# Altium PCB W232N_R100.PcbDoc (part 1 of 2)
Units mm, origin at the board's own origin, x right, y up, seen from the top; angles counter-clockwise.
Board outline 70 x 46.25 mm, 4 copper layers (Top Layer, Layer 1, Layer 2, Bottom Layer), stack 1.584 mm thick; 133 components, 105 nets, 435 pads, 346 vias.
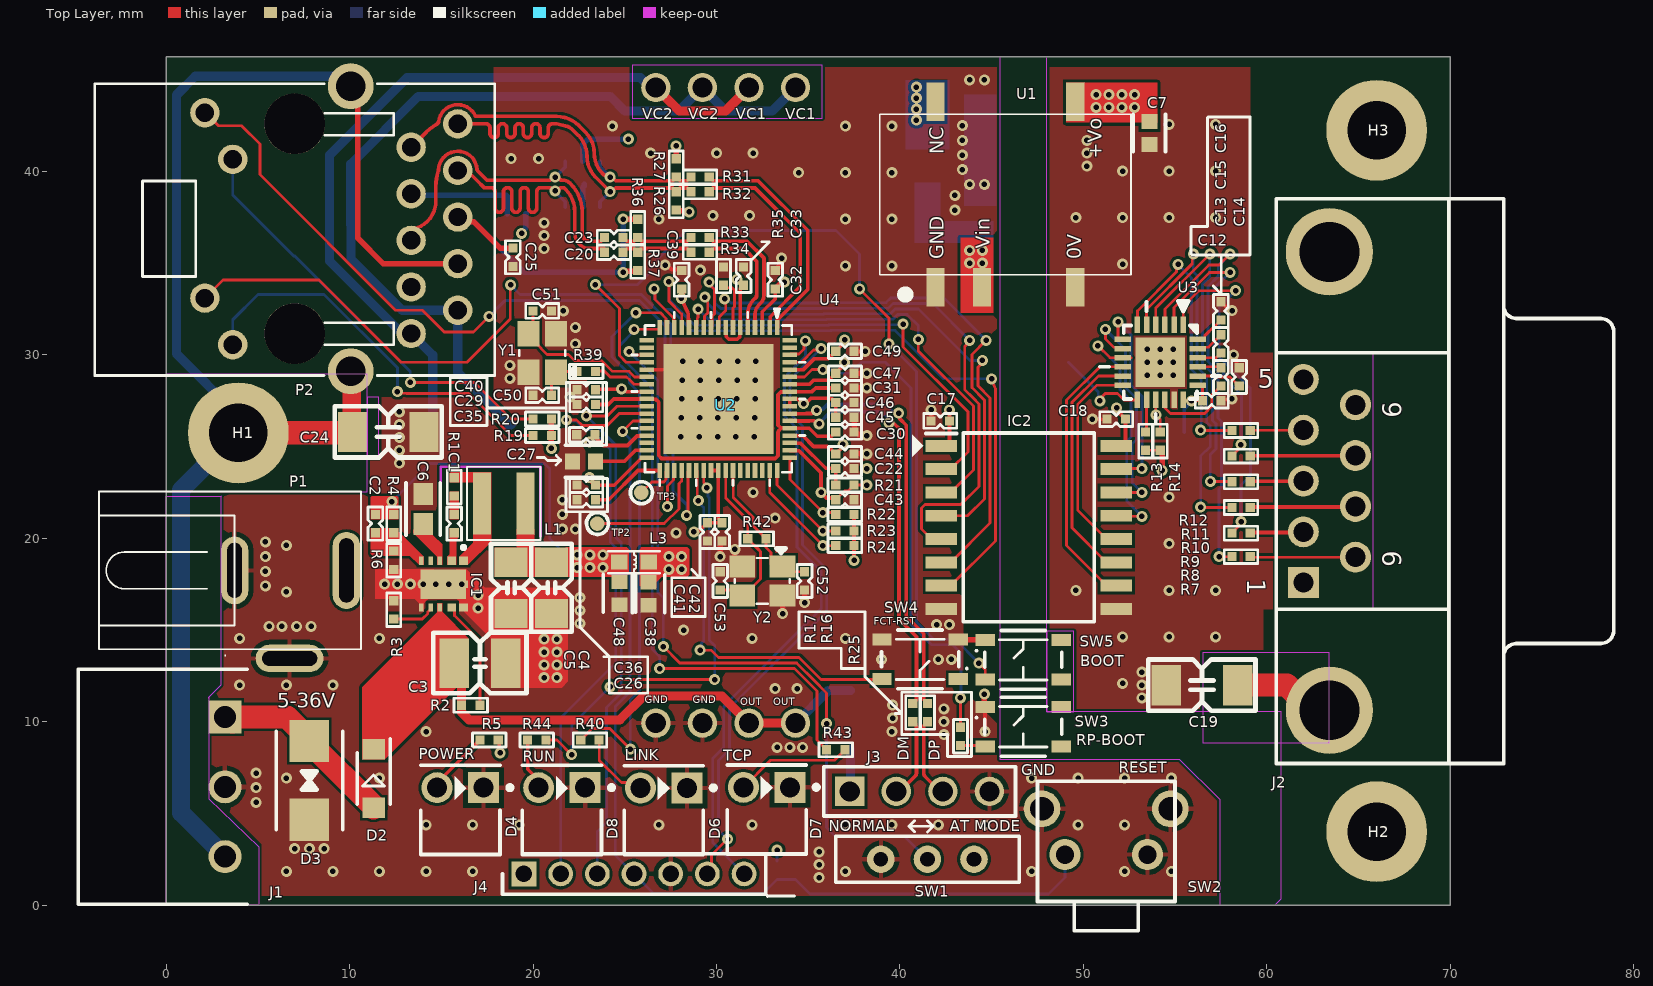
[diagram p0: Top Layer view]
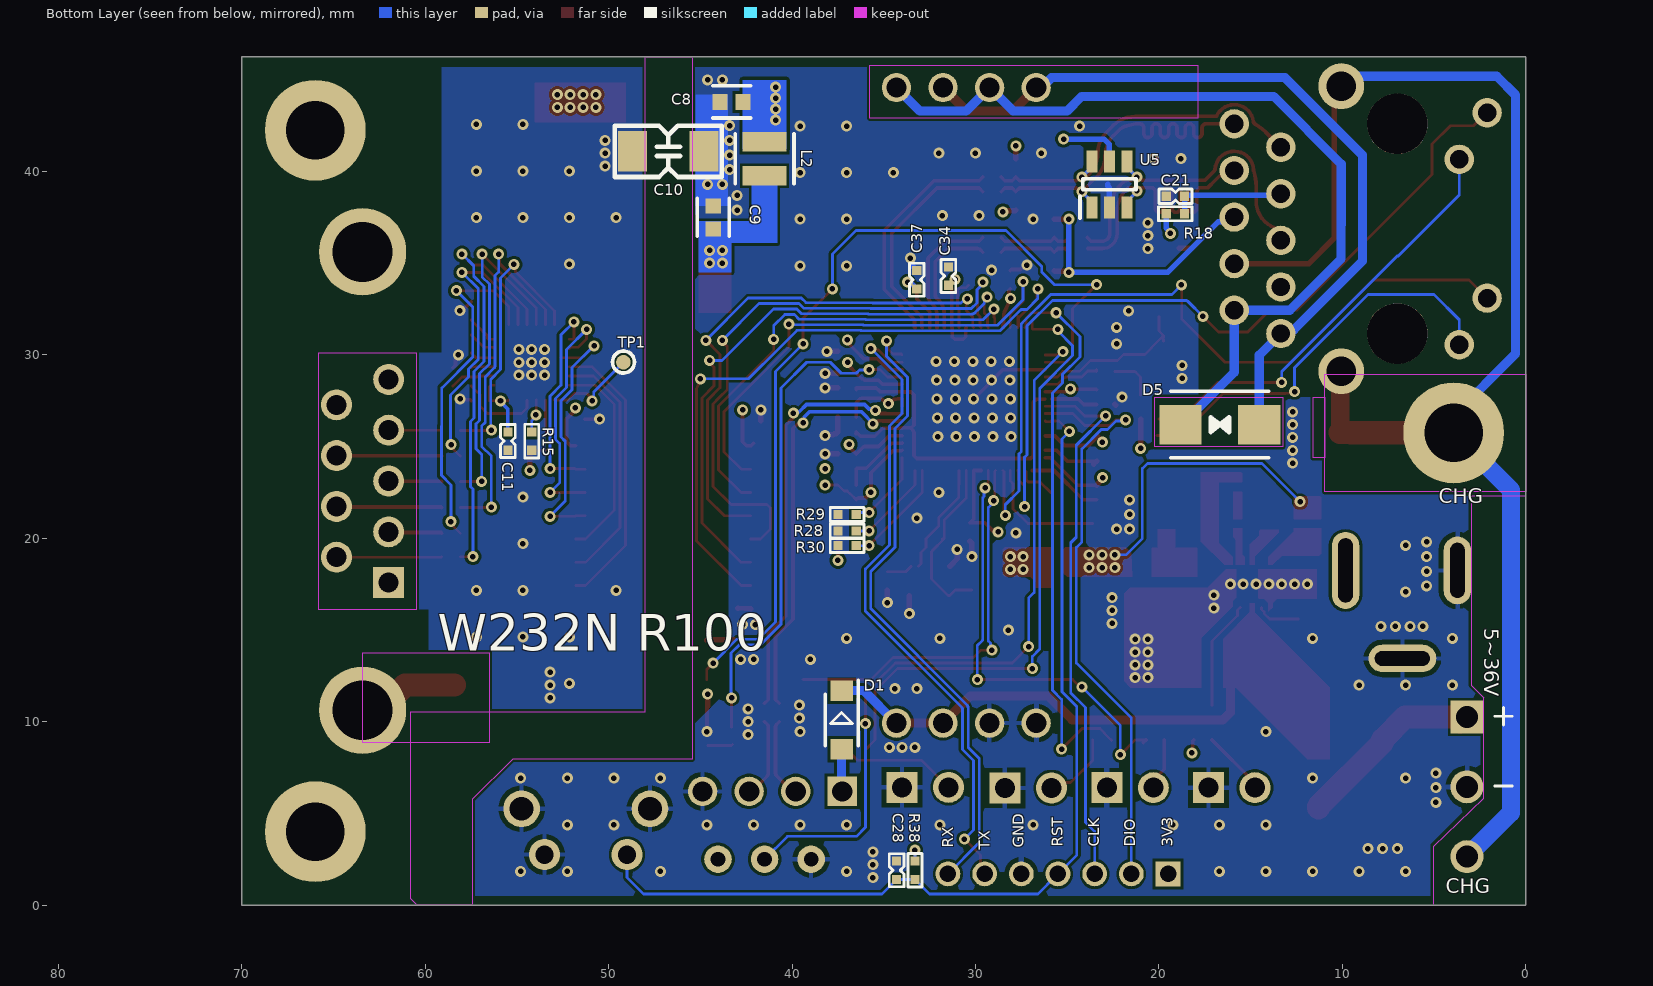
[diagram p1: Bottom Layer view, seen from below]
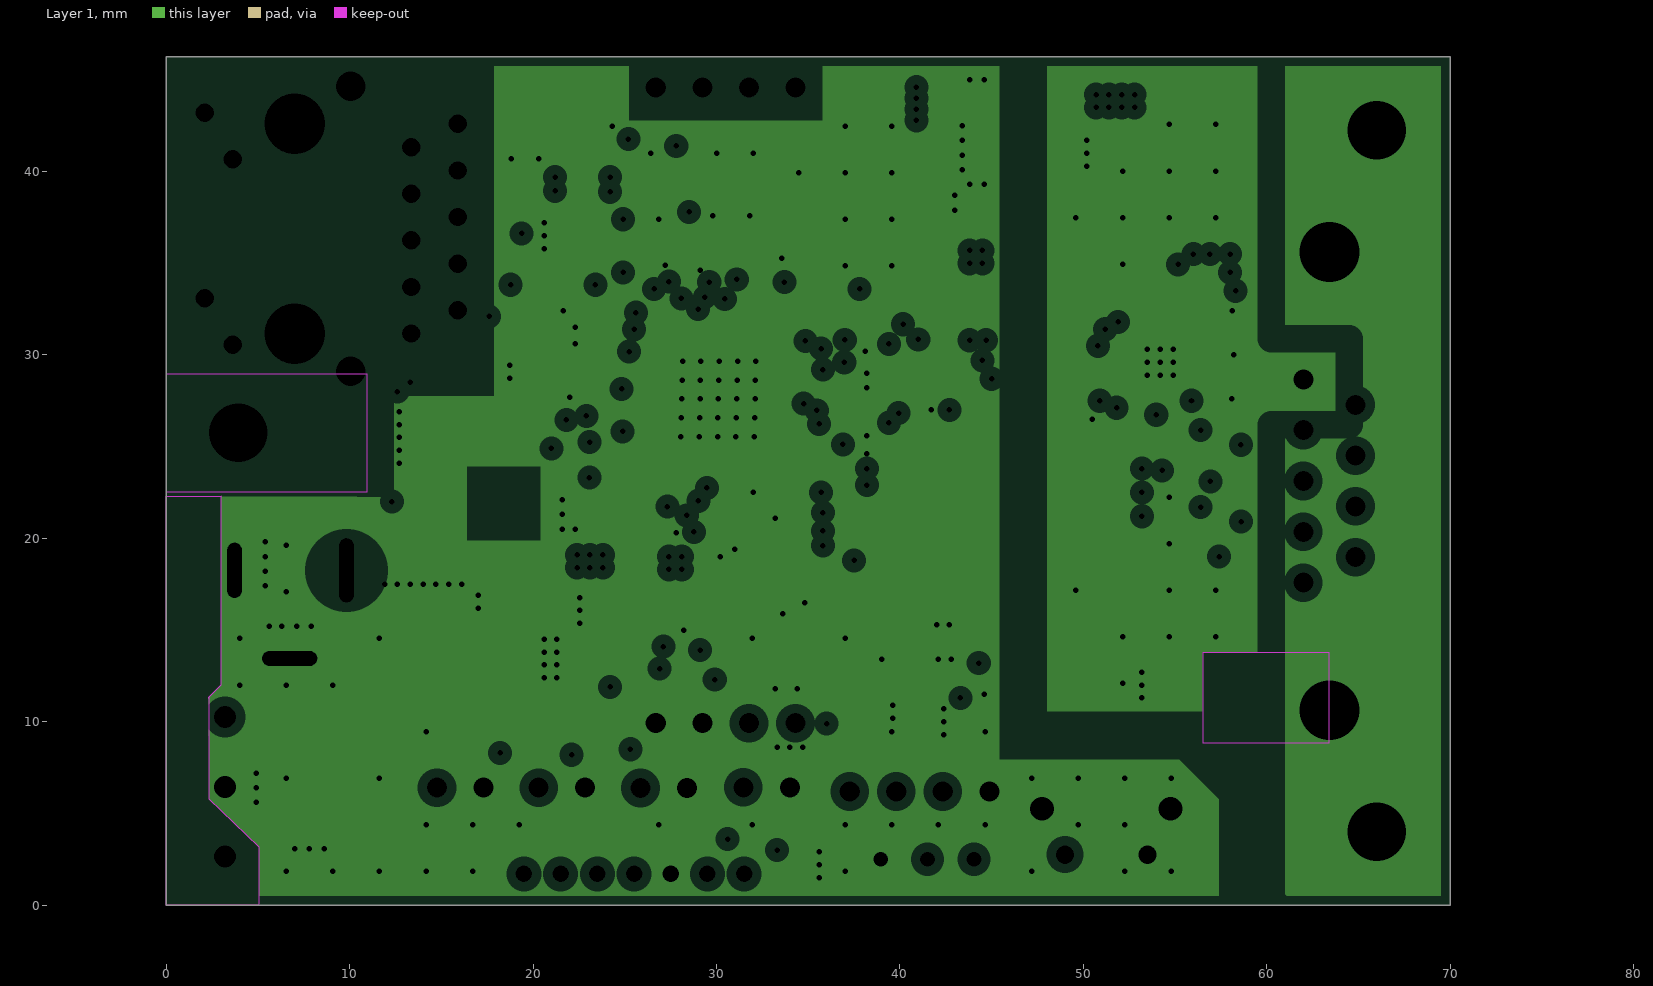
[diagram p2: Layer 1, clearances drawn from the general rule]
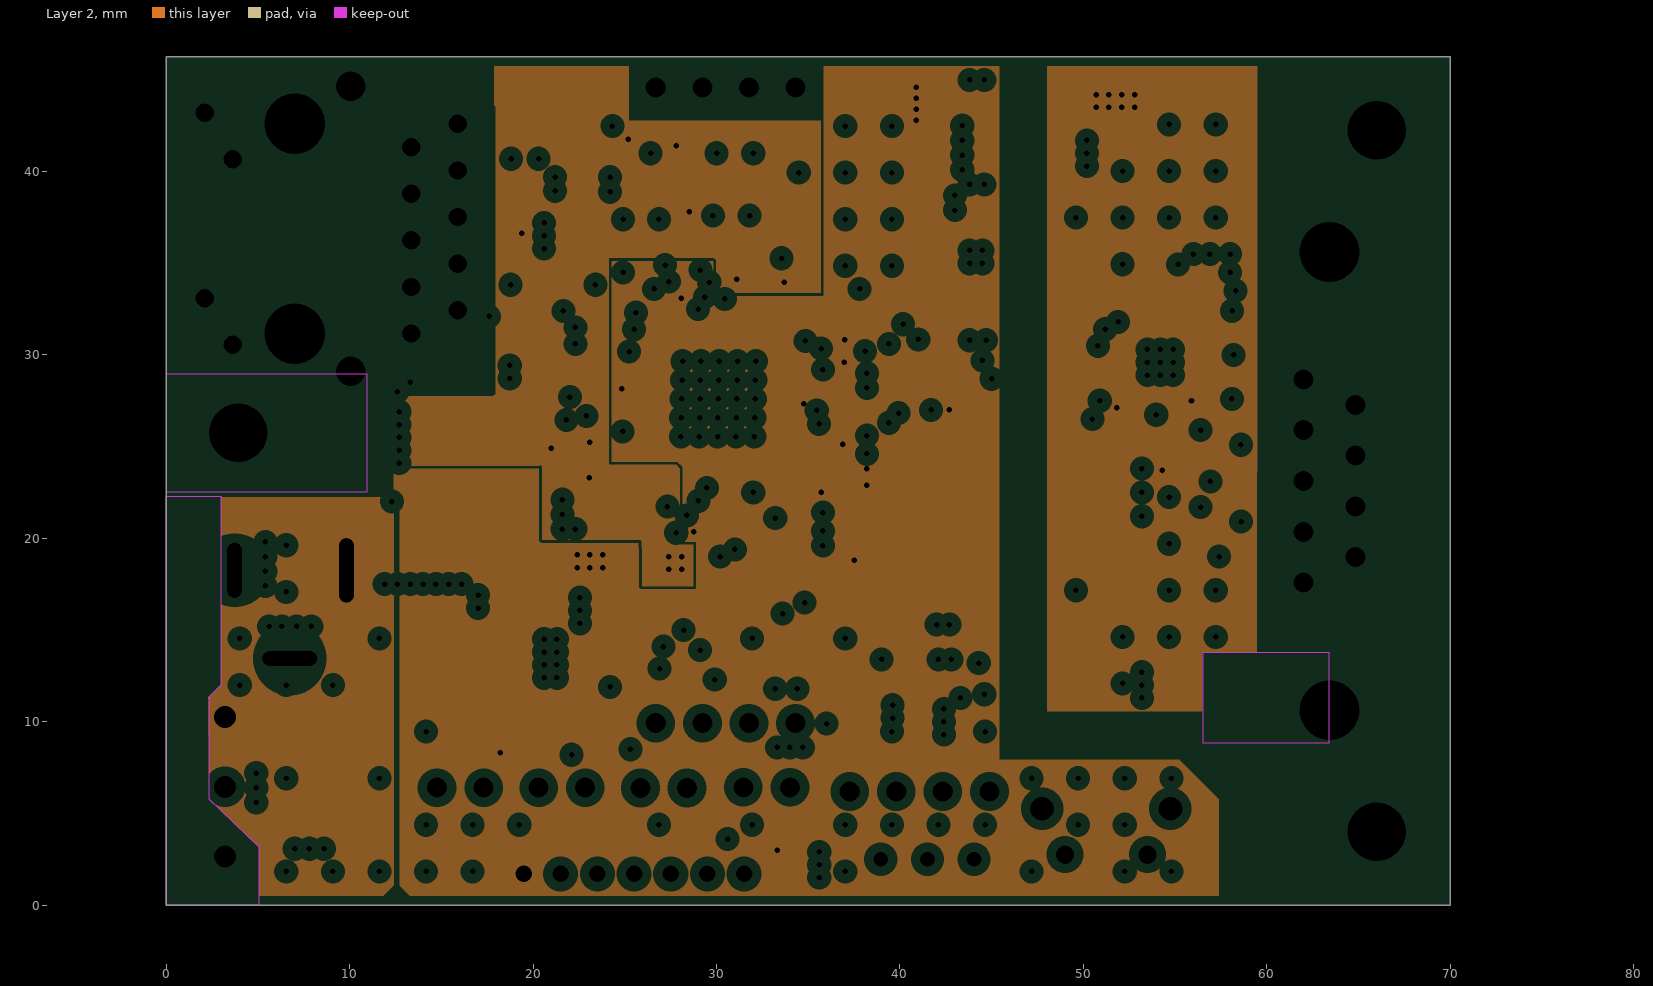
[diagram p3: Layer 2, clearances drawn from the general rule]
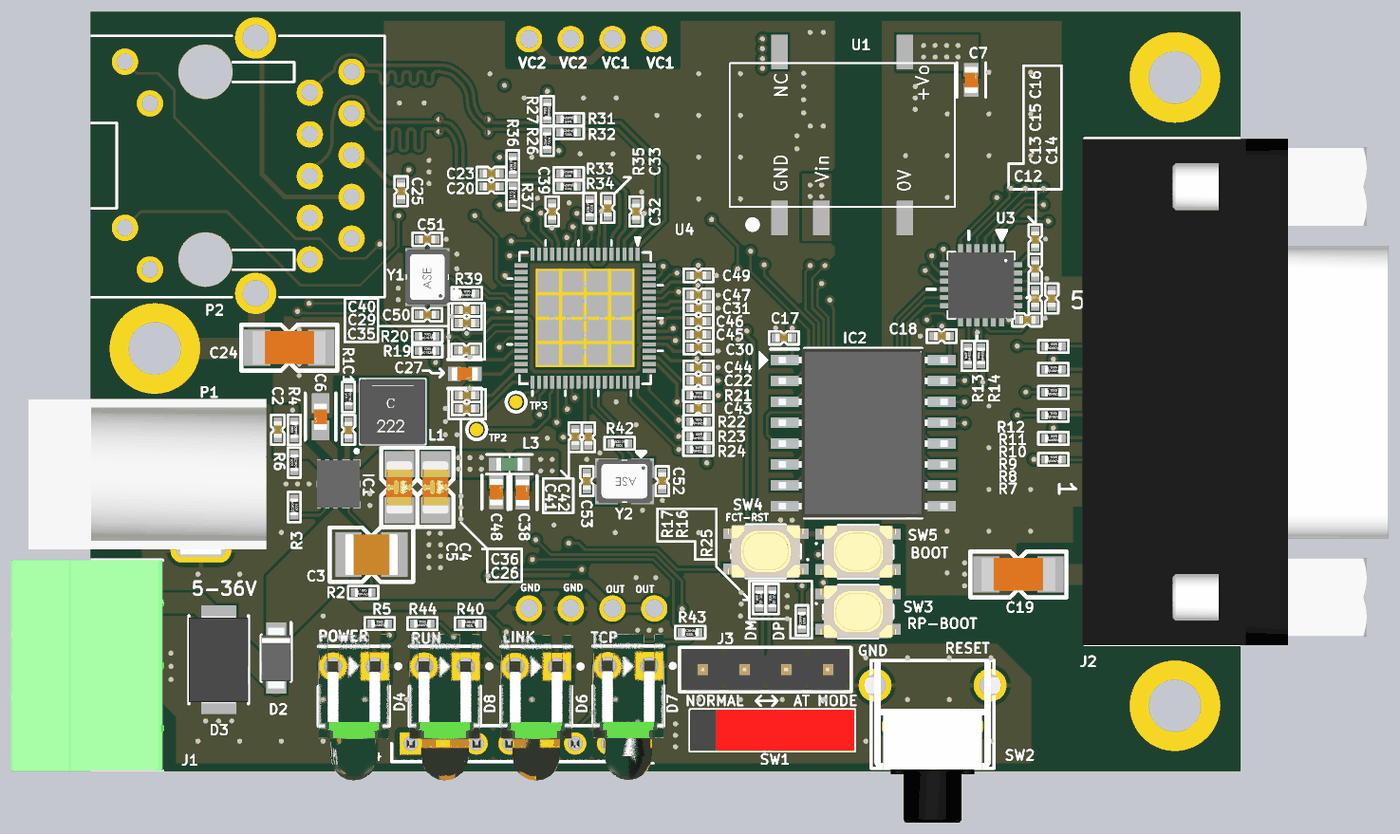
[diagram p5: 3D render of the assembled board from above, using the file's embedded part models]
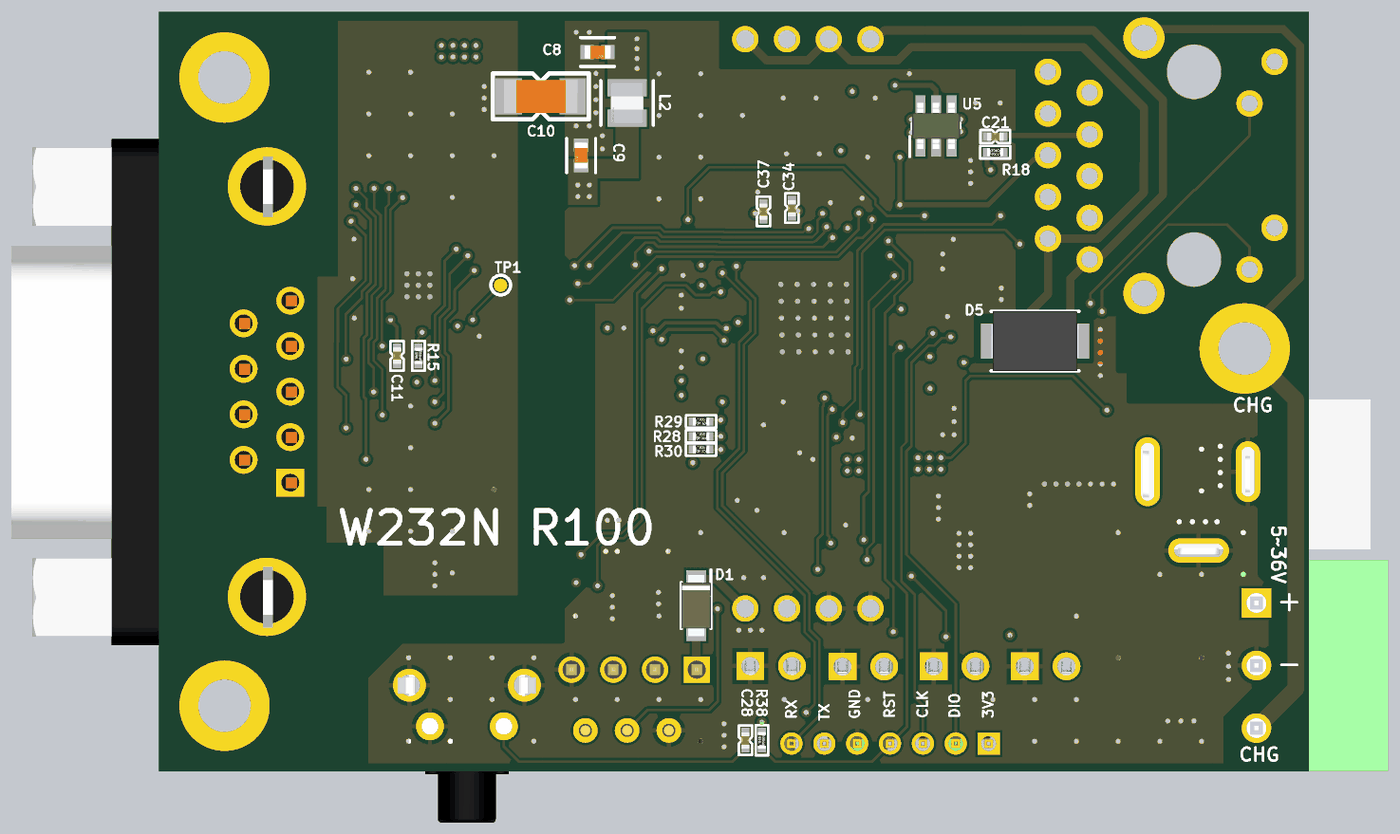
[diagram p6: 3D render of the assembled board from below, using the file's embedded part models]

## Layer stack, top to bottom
Top Solder: solder mask 0.0102, Solder Resist, Dk 3.5
Top Layer: signal copper 0.04
Dielectric 2: prepreg 0.2, PP-022, Dk 4.18
Layer 1: plane copper 0.032, net (Multiple Nets)
Dielectric 1: dielectric 1.04, FR-4, Dk 4.3
Layer 2: plane copper 0.032, net (Multiple Nets)
Dielectric 3: prepreg 0.2, PP-022, Dk 4.18
Bottom Layer: signal copper 0.04
Bottom Solder: solder mask 0.0102, Solder Resist, Dk 3.5

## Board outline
0,0 0,46.25 70,46.25 70,0

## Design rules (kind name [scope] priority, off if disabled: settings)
BoardOutlineClearance [InNetClass('All Nets')] p1: gap=0.3 ignorepadtopadclearanceinfootprint=FALSE
Clearance [All] p1: gap=0.15 ignorepadtopadclearanceinfootprint=FALSE except(0: Arc-Text Arc-Hole Track-Text Track-Hole SMDPad-Hole THPad-Hole Via-Hole Fill-Hole Poly-Hole Region-Hole Text-Hole; 0.1: SMDPad-Text THPad-Text Via-Text Fill-Text Poly-Text Region-Text Text-Text)
DiffPairsRouting [All] p1: maxlimit=0.2 minlimit=0.2 mostfreqgap=0.2 toplayer_minwidth=0.2 toplayer_maxwidth=0.2 toplayer_prefwidth=0.2 bottomlayer_minwidth=0.2 bottomlayer_maxwidth=0.2 bottomlayer_prefwidth=0.2 maxuncoupledlength=12.7
HoleSize [All] p1: absolutevalues=TRUE maxlimit=5 minlimit=0.025 maxpercent=80.000 minpercent=20.000
MinimumSolderMaskSliver [All] p1: minsoldermaskwidth=0.08
PlaneClearance [All] p1: clearance=0.508
PlaneConnect [All] p1: pad.planeconnectstyle=Relief pad.reliefexpansion=0.508 pad.reliefentries=4 pad.reliefconductorwidth=0.254 pad.reliefairgap=0.254 via.planeconnectstyle=Direct via.reliefexpansion=0.508 via.reliefentries=4 via.reliefconductorwidth=0.254 via.reliefairgap=0.254
PolygonConnect [All] p1: thpad.connectstyle=Relief thpad.reliefconductorwidth=0.254 thpad.reliefentries=4 thpad.polygonreliefangle="90 Angle" thpad.airgapwidth=0.254 smdpad.connectstyle=Direct smdpad.reliefconductorwidth=0.254 smdpad.reliefentries=4 smdpad.polygonreliefangle="90 Angle" smdpad.airgapwidth=0.254 via.connectstyle=Direct via.reliefconductorwidth=0.254 via.reliefentries=4 via.polygonreliefangle="90 Angle" via.airgapwidth=0.254
RoutingVias [All] p1: holewidth=0.3 width=0.6 viastyle="Through Hole" minholewidth=0.3 minwidth=0.6 maxholewidth=0.5 maxwidth=0.8
SilkToSilkClearance [All] p1: silktosilkclearance=0.01
SilkToSolderMaskClearance [IsText] p1: minsilkscreentomaskgap=0.1 clearancetoexposedcopper=TRUE
SolderMaskExpansion [All] p1: expansion=0 istentingtop=FALSE
Width [All] p1: maxlimit=3 minlimit=0.15 preferedwidth=0.152 minimp=50.000000 maximp=50.000000 favimp=50.000000
23 further rules are at their usual default settings.

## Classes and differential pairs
differential pair D: +D_P -D_N
differential pair MDI_R1: +MDI_R1_P -MDI_R1_N
differential pair T: +T_P -T_N
differential pair R: +R_P -R_N
differential pair MDI_T: +MDI_T_P -MDI_T_N
differential pair MDI_R: +MDI_R_P -MDI_R_N

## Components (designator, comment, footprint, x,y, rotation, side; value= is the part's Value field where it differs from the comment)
C1 "100nF" CAP-0402 15.7,20.8 r270 top
C2 "15pF" CAP-0402 11.4,20.8 r90 top
C3 "4.7uF / 100V" CAP-1210 17.1,13.2 r180 top
C4 "22uF/10V" CAP-1206 21,17.3 r270 top
C5 "22uF/10V" CAP-1206 18.8,17.3 r270 top
C6 "1uF" CAP-0603-1 14,21.6 r270 top
C7 "10uF/10V" CAP-0603-3 53.6,42.1 r90 top
C8 "4.7uF" CAP-0603-3 43.3,43.8 r180 bottom
C9 "4.7uF" CAP-0603-3 44.3,37.5 r270 bottom
C10 "1nF/2kV" CAP-1808 46.75,41.1 r180 bottom
C11 "100nF" CAP-0402 55.5,25.3 r90 bottom
C12 "100nF" CAP-0402 57,27.5 r0 top
C13 "100nF" CAP-0402 57.5,28.8 r270 top
C14 "100nF" CAP-0402 58.5,28.8 r270 top
C15 "100nF" CAP-0402 57.5,30.6 r90 top
C16 "100nF" CAP-0402 57.5,32.4 r270 top
C17 "100nF" CAP-0402 42.2,26.4 r180 top
C18 "100nF" CAP-0402 51.8,26.5 r0 top
C19 "1nF/2kV" CAP-1808 56.47,11.997 r180 top
C20 "6.8nF" CAP-0402 24.4,35.6 r180 top
C21 "22nF" CAP-0402 19.1,38.65 r180 bottom
C22 "2.2uF" CAP-0402 37,23.8 r180 top
C23 "6.8nF" CAP-0402 24.4,36.4 r180 top
C24 "1nF/2kV" CAP-1808 12.1,25.8 r180 top
C25 "10nF" CAP-0402 18.9,35.325 r90 top
C26 "10nF" CAP-0402 22.9,22.1 r0 top
C27 "4.7uF" CAP-0603-3 22.774,24.2 r0 top
C28 "100nF" CAP-0402 34.3,1.9 r270 bottom
C29 "2.2uF" CAP-0402 22.9,27.3 r0 top
C30 "100nF" CAP-0402 37,25.8 r180 top
C31 "100nF" CAP-0402 37,28.2 r180 top
C32 "100nF" CAP-0402 33.2,34.1 r270 top
C33 "100nF" CAP-0402 31.475,34.3 r270 top
C34 "100nF" CAP-0402 31.475,34.3 r270 bottom
C35 "100nF" CAP-0402 22.875,25.65 r0 top
C36 "100nF" CAP-0402 22.9,22.9 r0 top
C37 "100nF" CAP-0402 33.2,34.1 r270 bottom
C38 "10uF" CAP-0603-3 26.3,16.974 r90 top
C39 "2.2uF" CAP-0402 28.1,34.1 r270 top
C40 "2.2uF" CAP-0402 22.9,28.1 r0 top
C41 "2.2uF" CAP-0402 29.5,20.35 r90 top
C42 "100nF" CAP-0402 30.3,20.35 r90 top
C43 "100nF" CAP-0402 37,22.1 r180 top
C44 "100nF" CAP-0402 37,24.6 r180 top
C45 "100nF" CAP-0402 37,26.6 r180 top
C46 "100nF" CAP-0402 37,27.4 r180 top
C47 "100nF" CAP-0402 37,29 r180 top
C48 "10uF" CAP-0603-3 24.7,17 r90 top
C49 "100nF" CAP-0402 37,30.2 r180 top
C50 "15pF" CAP-0402 20.5,27.8 r0 top
C51 "15pF" CAP-0402 20.5,32.4 r180 top
C52 "18pF" CAP-0402 34.8,17.676 r90 top
C53 "18pF" CAP-0402 30.2,17.676 r270 top
D1 "SS1FN6-M3_I" SODFL3718X108N 37.3,10.1 r270 bottom
D2 "SS1FN6-M3_I" SODFL3718X108N 11.3,6.9 r270 top
D3 "SMBJ36CA" DO-214AA/SMB(TVS) 7.8,6.8 r90 top
D4 "RED" KLH-117 16.03,3.905 r0 top locked
D5 "SMBJ58CA" DO-214AA/SMB(TVS) 16.675,26.2 r0 bottom
D6 "GREEN" KLH-117 27.123,3.891 r0 top locked
D7 "GREEN" KLH-117 32.737,3.927 r0 top locked
D8 "GREEN" KLH-117 21.57,3.905 r0 top locked
H1 "PCB Hole" M3_HOLE 3.92,25.75 r0 top locked
H2 "PCB Hole" M3_HOLE 66,4 r0 top locked
H3 "PCB Hole" M3_HOLE 66,42.25 r0 top locked
IC1 "XC9702A75CDR-G" XC9135B18CDRG 15.1,17.5 r270 top
IC2 "ISO6763DWR" SOIC127P1030X265-16N 47.025,20.595 r0 top
J1 "Terminal_Blocks" 1803280 3.2,10.26 r270 top locked
J2 "D-SUB9-MALE" D-SUB9-MALE 72.92,23.125 r270 top locked
J3 "Pin Header Dip 4x1_2.54mm" Pin-Header(DIP)_4x1_2.54mm 41.07,6.2 r0 top locked
J4 "Pin Header 7x1_2.0mm" Pin-Header(DIP)_7x1_2.0mm 19.5,1.7 r0 top
L1 "VLS4020CX-220M-H" XAL40XX 18.4,21.9 r0 top
L2 "6.8uH" FP-SRN2512-MFG 41.5,40.7 r270 bottom
L3 "HH-1M1608-121JT" IND-0603 25.5,18.7 r0 top
P1 "DC-JACK 2pi" "DC-JACK 2PI" -0.08,18.25 r270 top locked
P2 "TRJ4284BHNL" RB1-ZZ-0049 7,36.882 r270 top locked
R1 "10R" RES-0402 15.7,22.8 r90 top
R2 "1K" RES-0402 16.6,10.9 r0 top
R3 "1K" RES-0402 12.4,16.1 r270 top
R4 "680k/1%" RES-0402 12.4,20.8 r90 top
R5 "330R" RES-0402 17.6,9 r0 top
R6 "200k/1%" RES-0402 12.4,18.8 r90 top
R7 "3R3" RES-0402 58.6,19 r0 top
R8 "3R3" RES-0402 58.6,20.281 r0 top
R9 "3R3" RES-0402 58.6,21.681 r0 top
R10 "3R3" RES-0402 58.6,23.081 r0 top
R11 "3R3" RES-0402 58.6,24.481 r0 top
R12 "3R3" RES-0402 58.6,25.881 r0 top
R13 "1K" RES-0402 53.4,25.3 r90 top
R14 "1K" RES-0402 54.2,25.3 r90 top
R15 "NC" RES-0402 54.2,25.3 r90 bottom
R16 "27R" RES-0402 41.5,10.5 r90 top
R17 "27R" RES-0402 40.7,10.5 r90 top
R18 "10R 1%" RES-0402 19.1,37.7 r0 bottom
R19 "330R" RES-0402 20.5,25.6 r0 top
R20 "330R" RES-0402 20.5,26.5 r0 top
R21 "200R" RES-0402 37,22.9 r0 top
R22 "0R" RES-0402 37,21.3 r0 top
R23 "0R" RES-0402 37,20.4 r0 top
R24 "0R" RES-0402 37,19.6 r0 top
R25 "1K" RES-0402 43.3,9.2 r270 top
R26 "49.9R 1%" RES-0402 27.8,38.4 r270 top
R27 "49.9R 1%" RES-0402 27.8,40.2 r90 top
R28 "NC" RES-0402 37,21.3 r180 bottom
R29 "NC" RES-0402 37,20.4 r180 bottom
R30 "NC" RES-0402 37,19.6 r180 bottom
R31 "3R3" RES-0402 29.1,39.7 r180 top
R32 "3R3" RES-0402 29.1,38.9 r180 top
R33 "3R3" RES-0402 29.1,36.4 r180 top
R34 "3R3" RES-0402 29.1,35.6 r180 top
R35 "12.4K 1%" RES-0402 30.375,34.3 r270 top
R36 "49.9R 1%" RES-0402 25.7,36.9 r270 top
R37 "49.9R 1%" RES-0402 25.7,35.1 r90 top
R38 "4.7K" RES-0402 33.3,1.9 r90 bottom
R39 "1K" RES-0402 22.9,29.1 r0 top
R40 "330R" RES-0402 23.1,9 r180 top
R42 "1M" RES-0402 32.2,19.976 r180 top
R43 "330R" RES-0402 36.5,8.471 r180 top
R44 "330R" RES-0402 20.2,9 r0 top
SW1 "ITS-12H" ITS-12H 41.5,2.5 r0 top
SW2 "IT-1102VA" IT-1102VA 51.25,2.75 r0 top locked
SW3 "1188(SMD)" 1188 46.725,9.725 r0 top
SW4 "1188(SMD)" 1188 41.1,13.4 r180 top
SW5 "1188(SMD)" 1188 46.725,13.375 r0 top
TP1 "TPS" TPS 49.2,29.6 r0 bottom
TP2 "TPS" TPS 23.5,20.8 r180 top
TP3 "TPS" TPS 25.893,22.495 r90 top
U1 "B0303XT-1WR3" IB05_XT-W75R3 45.75,38.75 r0 top locked
U2 "WIZPoE" WIZPOE 22.5,46.251 r270 top locked
U3 "XR32330EBERTR-F" QFN24(0.5/4X4) 54.2,29.6 r270 top
U4 "W55RP20" QFN68(0.4/8X8) 30.1,27.6 r270 top locked
U5 "TPD4S009DBVR" SOT95P280X145-6N 22.7,39.3 r90 bottom
Y1 "12MHz" OSC-TZ1067B 20.5,30.1 r90 top
Y2 "25MHz" OSC-82J0626 32.5,17.676 r180 top

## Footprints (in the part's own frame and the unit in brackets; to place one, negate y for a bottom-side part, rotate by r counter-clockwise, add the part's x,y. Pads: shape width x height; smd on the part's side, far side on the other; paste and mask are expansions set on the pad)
1188 [mm]
  rect 1.05x0.65 smd: 1(-2.075,1.075) 2(2.075,1.075) 3(-2.075,-1.075) 4(2.075,-1.075)
  silkscreen extent -2.6,-1.6 2.1,1.6, body extent -2.3,-1.6 2.3,1.6, height 2.53
1803280 [mm]
  rect 1.8x1.8 hole 1.2: 1(0,0)
  round 1.8 hole 1.2: 2(3.81,0) 3(7.62,0)
  silkscreen extent -3.38,-8 10.22,1.2, body extent -2.6,-8 10.22,1.3, height 7.26
CAP-0402 [mm]
  rect 0.5x0.5 smd: 1(-0.5,0) 2(0.5,0)
  silkscreen extent -0.9,-0.4 0.9,0.4, body extent -0.48,-0.25 0.52,0.25, height 0.6
CAP-0603-1 [mil]
  rect 47.5x42.06 smd paste+0 mask+0: 1(-32.51,0) 2(32.51,0)
  silkscreen extent -56,-37 56,37, body extent -76,-41 76,41, height 10
CAP-0603-3 [mm]
  rect 0.807x0.868 smd paste+0 mask+0: 1(-0.626,0) 2(0.626,0)
  silkscreen extent -1.03,-0.88 1.03,0.88, body extent -1.13,-0.58 1.13,0.58, height 0.25
CAP-1206 [mm]
  rect 1.6x1.8 smd: 1(-1.4,0) 2(1.4,0)
  silkscreen extent -2.4,-1.1 2.4,1.1, body extent -1.6,-0.8 1.6,0.8, height 1
CAP-1210 [mm]
  rect 1.6x2.7 smd: 1(-1.4,0) 2(1.4,0)
  silkscreen extent -2.54,-1.65 2.54,1.65, body extent -1.6,-1.25 1.6,1.25, height 1.3
CAP-1808 [mm] "Ceramic CAP 1808(4520)"
  rect 1.6x2.2 smd: 1(-1.95,0) 2(1.95,0)
  silkscreen extent -2.92,-1.4 2.92,1.4, body extent -2.25,-1.02 2.25,1.01, height 2
D-SUB9-MALE [mm] "D-SUB9, MALE, Right Angle;"
  rect 1.69x1.69 hole 1.09: 1(5.54,-10.92)
  round 1.69 hole 1.09: 2(2.77,-10.92) 3(0,-10.92) 4(-2.77,-10.92) 5(-5.54,-10.92) 6(4.155,-8.08) 7(1.385,-8.08) 8(-1.385,-8.08) 9(-4.155,-8.08)
  round 4.76 hole 3.26: 10(-12.495,-9.5) 11(12.495,-9.5)
  silkscreen extent -15.4,-12.4 15.4,6, body extent -15.38,-12.55 15.43,6.05, height 12.57
"DC-JACK 2PI" [mm] "DC-JACK 2pi"
  oval 4.2x1.5 hole 0.8 slot 3.5 at 0 deg: 1(0,9.9)
  oval 1.5x3.7 hole 0.8 slot 3 at 90 deg: 2(4.8,6.8)
  oval 3.7x1.5 hole 0.8 slot 3 at 0 deg: 3(0,3.8)
  silkscreen extent -4.3,-3.6 4.3,10.7, body extent -4.42,-3.69 5.05,10.79, height 11.18
DO-214AA/SMB(TVS) [mm]
  rect 2.3x2.15 smd: 1(-2.15,0) 2(2.15,0)
  silkscreen extent -2.68,-1.81 2.68,1.81, body extent -2.67,-1.81 2.68,1.81, height 2.65
FP-SRN2512-MFG [mm]
  rect 1.05x2.4 smd paste+0 mask+0: 1(-0.925,0) 2(0.925,0)
  silkscreen extent -1.35,-1.6 1.35,1.6, body extent -1.25,-1 1.25,1, height 1.2
IB05_XT-W75R3 [mm]
  rect 1x2.1 smd: 1(-3.81,-5.05) 2(-1.27,-5.05) 4(3.81,-5.05) 5(3.81,5.05) 8(-3.81,5.05)
  silkscreen extent -6.85,-5.65 6.85,4.38
IND-0603 [mm] "Inductor 0603(1608)"
  rect 0.89x0.82 smd: 1(-0.8,0) 2(0.8,0)
  silkscreen extent -1.4,-0.6 1.4,0.6, body extent -0.8,-0.4 0.8,0.4, height 0.95
IT-1102VA [mm]
  round 1.7 hole 1: 1(-2.25,0) 2(2.25,0)
  round 2 hole 1.3: 3(-3.5,2.5) 4(3.5,2.5)
  silkscreen extent -3.75,-4.15 3.75,4, body extent -4.2,-5.86 4.2,4, height 7.06
ITS-12H [mm] "Through Hole Slide Switch SPDT On-On 500mA Slide"
  round 1.5 hole 0.8: 1(0,0) 2(2.54,0) 3(-2.54,0)
  silkscreen extent -5,-1.25 5,1.25, body extent -5,-1.25 5,1.25, height 6.4
KLH-117 [mm]
  rect 1.69x1.69 hole 1.09 paste-1000 mask+0: 1(1.27,2.495)
  round 1.69 hole 1.09 paste-1000 mask+0: 2(-1.27,2.495)
  silkscreen extent -2.16,-1.14 2.83,3.71, body extent -2.26,-4.54 2.26,4.54, height 0.25
M3_HOLE [mm]
  round 5.5 hole 3.2: 1(0,0)
OSC-82J0626 [mm]
  rect 1.4x1.2 smd: 1(-1.1,-0.8) 2(1.1,-0.8) 3(1.1,0.8) 4(-1.1,0.8)
  silkscreen extent -1.5,-1.78 1.5,1.25, body extent -1.7,-1.35 1.7,1.35, height 1.06
OSC-TZ1067B [mm]
  rect 1.4x1.2 smd: 1(-1.05,-0.75) 2(1.05,-0.75) 3(1.05,0.75) 4(-1.05,0.75)
  silkscreen extent -1.27,-1.78 0.15,1.25, body extent -1.7,-1.35 1.7,1.35, height 1.06
Pin-Header(DIP)_4x1_2.54mm [mm] "Pin Header, pitch 2.54 mm, THT, Vertical, single row, 4p"
  rect 1.6x1.6 hole 1.1: 1(-3.81,0)
  round 1.6 hole 1.1: 2(-1.27,0) 3(1.27,0) 4(3.81,0)
  silkscreen extent -5.23,-1.35 5.23,1.35, body extent -5.08,-1.27 5.08,1.27, height 8.57
Pin-Header(DIP)_7x1_2.0mm [mm]
  rect 1.35x1.35 hole 0.9: 1(0,0)
  round 1.35 hole 0.9: 2(2,0) 3(4,0) 4(6,0) 5(8,0) 6(10,0) 7(12,0)
  silkscreen extent -1.17,-1.1 13.18,1.1, body extent -1,-1 13,1, height 5
QFN24(0.5/4X4) [mm] "QFN-24 Package with 4x4mm Body and 0.5mm Pitch"
  rect 0.9x0.3 smd: 1(-2.05,1.25) 2(-2.05,0.75) 3(-2.05,0.25) 4(-2.05,-0.25) 5(-2.05,-0.75) 6(-2.05,-1.25) 13(2.05,-1.25) 14(2.05,-0.75) 15(2.05,-0.25) 16(2.05,0.25) 17(2.05,0.75) 18(2.05,1.25)
  rect 0.3x0.9 smd: 7(-1.25,-2.05) 8(-0.75,-2.05) 9(-0.25,-2.05) 10(0.25,-2.05) 11(0.75,-2.05) 12(1.25,-2.05) 19(1.25,2.05) 20(0.75,2.05) 21(0.25,2.05) 22(-0.25,2.05) 23(-0.75,2.05) 24(-1.25,2.05)
  rect 2.7x2.7 smd: 25(0,0)
  silkscreen extent -3.35,-3.3 3.3,3.3, body extent -2,-2 2,2, height 0.9
QFN68(0.4/8X8) [mm]
  rect 0.8x0.25 smd mask+0: 1(-3.9,3.2) 2(-3.9,2.8) 3(-3.9,2.4) 4(-3.9,2) 5(-3.9,1.6) 6(-3.9,1.2) 7(-3.9,0.8) 8(-3.9,0.4) 9(-3.9,0) 10(-3.9,-0.4) 11(-3.9,-0.8) 12(-3.9,-1.2) 13(-3.9,-1.6) 14(-3.9,-2) 15(-3.9,-2.4) 16(-3.9,-2.8) 17(-3.9,-3.2) 35(3.9,-3.2) 36(3.9,-2.8) 37(3.9,-2.4) 38(3.9,-2) 39(3.9,-1.6) 40(3.9,-1.2) 41(3.9,-0.8) 42(3.9,-0.4) 43(3.9,0) 44(3.9,0.4) 45(3.9,0.8) 46(3.9,1.2) 47(3.9,1.6) 48(3.9,2) 49(3.9,2.4) 50(3.9,2.8) 51(3.9,3.2)
  rect 0.25x0.8 smd mask+0: 18(-3.2,-3.9) 19(-2.8,-3.9) 20(-2.4,-3.9) 21(-2,-3.9) 22(-1.6,-3.9) 23(-1.2,-3.9) 24(-0.8,-3.9) 25(-0.4,-3.9) 26(0,-3.9) 27(0.4,-3.9) 28(0.8,-3.9) 29(1.2,-3.9) 30(1.6,-3.9) 31(2,-3.9) 32(2.4,-3.9) 33(2.8,-3.9) 34(3.2,-3.9) 52(3.2,3.9) 53(2.8,3.9) 54(2.4,3.9) 55(2,3.9) 56(1.6,3.9) 57(1.2,3.9) 58(0.8,3.9) 59(0.4,3.9) 60(0,3.9) 61(-0.4,3.9) 62(-0.8,3.9) 63(-1.2,3.9) 64(-1.6,3.9) 65(-2,3.9) 66(-2.4,3.9) 67(-2.8,3.9) 68(-3.2,3.9)
  rect 6x6 smd paste-4 mask+0: 69(0,0)
  silkscreen extent -4.91,-4.72 4.72,4.72, body extent -4,-4 4,4, height 0.9
RB1-ZZ-0049 [mm]
  round 3.3 hole 3.3: 0(-5.715,0) 0(5.715,0)
  round 1.6 hole 1: L1(6.325,-3.38) L2(3.785,-4.9) L3(-3.785,-3.38) L4(-6.325,-4.9) R1(-5.715,8.89) R2(-4.445,6.35) R3(-3.175,8.89) R4(-1.905,6.35) R5(-0.635,8.89) R6(0.635,6.35) R7(1.905,8.89) R8(3.175,6.35) R9(4.445,8.89) R10(5.715,6.35)
  round 2.5 hole 1.6: S1(-7.775,3.05) S2(7.775,3.05)
  Top Layer pour cut-out: -6.3,1.65 -6.3,5.4 -5.1,5.4 -5.1,1.65
  Top Layer pour cut-out: 5.13,1.65 5.13,5.4 6.33,5.4 6.33,1.65
  Top Layer pour cut-out: -2.6,-8.3 -2.6,-5.4 2.6,-5.4 2.6,-8.3
  Top Layer pour cut-out: -8.8,-7.6 8.8,-7.6 8.8,-4.6 -8.8,-4.6
  silkscreen extent -7.9,-10.9 8,10.9, body extent -7.9,-10.9 8,10.9, height 13.35
RES-0402 [mm]
  rect 0.5x0.5 smd: 1(-0.5,0) 2(0.5,0)
  silkscreen extent -0.91,-0.38 0.91,0.38, body extent -0.5,-0.25 0.5,0.25, height 0.35
SODFL3718X108N [mm]
  rect 1.12x1.22 smd: 1(-1.6,0) 2(1.6,0)
  silkscreen extent -2.16,-0.9 1.4,0.9, body extent -1.85,-0.9 1.85,0.9, height 1.08
SOIC127P1030X265-16N [mm]
  rect 1.7x0.65 smd: 1(-4.775,4.445) 2(-4.775,3.175) 3(-4.775,1.905) 4(-4.775,0.635) 5(-4.775,-0.635) 6(-4.775,-1.905) 7(-4.775,-3.175) 8(-4.775,-4.445) 9(4.775,-4.445) 10(4.775,-3.175) 11(4.775,-1.905) 12(4.775,-0.635) 13(4.775,0.635) 14(4.775,1.905) 15(4.775,3.175) 16(4.775,4.445)
  silkscreen extent -5.63,-5.15 3.57,5.15, body extent -5.15,-5.15 5.15,5.15, height 2.65
SOT95P280X145-6N [mm]
  rect 1.2x0.6 smd: 1(-1.25,0.95) 2(-1.25,0) 3(-1.25,-0.95) 4(1.25,-0.95) 5(1.25,0) 6(1.25,0.95)
  silkscreen extent -1.85,-1.45 0.3,1.6, body extent -1.4,-1.45 1.4,1.45, height 1.2
TPS [mm]
  round 0.8 smd paste-1: 1(0,0)
  silkscreen extent -0.61,-0.61 0.59,0.59
WIZPOE [mm]
  round 1.6 hole 1.1: 1(1.67,11.81) 2(1.67,9.27) 3(1.67,6.73) 4(1.67,4.19) 5(36.33,4.19) 6(36.33,6.73) 7(36.33,9.27) 8(36.33,11.81)
XAL40XX [mm]
  rect 0.98x3.4 smd: 1(-1.185,0) 2(1.185,0)
  silkscreen extent -2,-2 2,2, body extent -2,-2 2,2, height 2.1
XC9135B18CDRG [mm]
  rect 0.45x0.475 smd: 1(-1.275,1.106) 2(-1.275,0.456) 9(1.275,0.456) 10(1.275,1.106)
  rect 0.45x0.25 smd: 3(-1.275,-0.194) 4(-1.275,-0.694) 5(-1.275,-1.194) 6(1.275,-1.194) 7(1.275,-0.694) 8(1.275,-0.194)
  rect 1.6x2.5 smd: 11(0,0)
  rect 0.4x0.1 smd: A11(0,1.3) B11(0,-1.3)
  silkscreen extent -2.1,1 -1.9,1.2, body extent -1.45,-1.3 1.45,1.3, height 0.7

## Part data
C1 C2 C11 C12 C13 C14 C15 C16 C17 C18 C20 C21 C22 C23 C25 C26 C28 C29 C30 C31 C32 C33 C34 C35 C36 C37 C39 C40 C41 C42 C43 C44 C45 C46 C47 C49 C50 C51 C52 C53: library part CAP-0402, "MLCC-0402(1005)"
C3: library part CAP-1210, "MLCC-1210(3225)"
C4 C5: library part CAP-1206, "MLCC-1206(3216)", Capacitance=1nF, Case Code (Imperial)=1206, Case Code (Metric)=3216, Dielectric=X7R, Dielectric Material=Ceramic, Manufacturer=KEMET, Manufacturer Part Number=C1206X102KGRACTU, Max Operating Temperature=125°C, Min Operating Temperature=-55°C, Package Quantity=1, Tolerance=10%, Voltage Rating=2kV
C6 C7 C8 C9 C27 C38 C48: library part CAP-0603, "MLCC-0603(1608)"
C10 C19 C24: library part CAP-1808, "MLCC-1808(4520)"
D1 D2: "Schottky Diode", Arrow Part Number=SS1FN6-M3/I, Manufacturer_Name=Vishay, Mouser Part Number=78-SS1FN6-M3/I
D3: library part "DIODE-TVS (SMB)", Manufacturer="Vishay Semiconductor", Manufacturer Part Number=SMAJ58CA-E3/61, Operating Junction and Storage Temperature Range="-55 to 150 degC"
D4 D6 D7 D8: library part KLH-117, "LED 3MM HIGH EFF GREEN", Color=Green, Current=10mA, Forward Voltage=2.1V, Manufacturer=Dialight, Manufacturer Part Number=551-0207F, Max Operating Temperature=85°C, Min Operating Temperature=-25°C, Package Quantity=100, Power Dissipation=75mW, Reverse Voltage=3V
D5: library part "DIODE-TVS (SMB)", Manufacturer="Vishay Semiconductors", Manufacturer Part Number=SMAJ58CA-E3/61, Operating Junction and Storage Temperature Range="-55 to 150 degC"
H1 H2 H3: "PCB Supporter Hole"
IC1: "Integrated Circuit", Manufacturer_Name=Torex, Mouser Part Number=865-XC9702A75CDR-G
IC2: "Integrated Circuit", Manufacturer_Name="Texas Instruments", Mouser Part Number=595-ISO6763DWR
J1: library part 1803280, "Connector", Manufacturer_Name="Phoenix Contact", Mouser Part Number=651-1803280
J2: "D-SUB-9, MALE,  Right Angle", PackageDocument=O
J3: library part "Pin Header 4x1_2.54mm", "THT Vertical Pin Header WR-PHD, Pitch 2.54 mm, Single Row, 4 pins", Contact Resistance=20mOhm, Manufacturer="Wurth Elektronik", Operating Temperature=-40to105degC, Package Reference=61300411121, Rated Current=3A, Withstanding Voltage=500VAC, Working Voltage=250VAC
J4: "Connector", Manufacturer_Name=Harwin, Manufacturer_Part_Number=M22-2010705, Mouser Part Number=855-M22-2010705
L1: library part XAL4040-822MEC, "Inductor", Manufacturer_Name=COILCRAFT, Mouser Part Number=994-XAL4040-822MEC
L2: library part IND-1008(2520), "SMD IND 1008(2520)", Case Code (Imperial)=1008, Case Code (Metric)=2520, Current Rating=4.7A, DC Resistance (DCR)=24mR, Inductance=240nH, Inductance Tolerance=20%, Max Operating Temperature=125°C, Min Operating Temperature=-55°C, Package Quantity=2000, Resistor Type=Wirewound, Saturation Current=8A, Self Resonant Frequency=330MHz, Test Frequency=1MHz
L3: library part IND-0603, "Inductor 0603(1608)"
P2: library part RB1-ZZ-0049, "PoE RJ45"
R1 R2 R3 R4 R5 R6 R7 R8 R9 R10 R11 R12 R13 R14 R15 R16 R17 R18 R19 R20 R21 R22 R23 R24 R25 R26 R27 R28 R29 R30 R31 R32 R33 R34 R35 R36 R37 R38 R39 R40 R42 R43 R44: library part RES-0402, "Chip Resistor 0402(1005)"
SW1: "Slide Switch"
SW2: "IT-1102VA-3.85MM"
SW3 SW4 SW5: "SMD TACT SWITCH"
TP1 TP2 TP3: "Test_point", Contact Resistance=20mOhm, Manufacturer="Wurth Elektronik", Operating Temperature=-40to105degC, Package Reference=61300211121, Rated Current=3A, Withstanding Voltage=500VAC, Working Voltage=250VAC
U1: library part IES0103S3V3, "Isolate DCDC"
U3: "3-Driver/3-Receiver RS232 Transceiver"
U4: library part W55RP20_2, "WIZnet Hardwired TCP/IP Chip"
U5: "Integrated Circuit", Manufacturer_Name="Texas Instruments", Mouser Part Number=595-TPD4S009DBVR
Y1: library part OSC-TZ1067B-12MHz, "X-tal 12MHz,3.2x2.5 SMD, CL=20pF"
Y2: library part OSC-82J0626-25MHz, "X-tal 25MHz,3.2x2.5 SMD, CL=18pF"

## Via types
v1: diameter 0.6, hole 0.3, Top Layer to Bottom Layer, tented both sides, 346 vias

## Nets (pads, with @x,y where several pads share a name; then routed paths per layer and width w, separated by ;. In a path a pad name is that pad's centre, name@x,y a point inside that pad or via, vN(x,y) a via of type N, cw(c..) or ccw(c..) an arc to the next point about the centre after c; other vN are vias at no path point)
1V1: C29.2 C30.2 C31.2 U4.26 U4.56 U4.61 | length 22.8
  Top Layer w0.15: U4.26@26.2,27.6 U4.26@26.225,27.575
  Top Layer w0.2: C29.2@23.4,27.3 24.097,27.3 24.397,27.6 25.2,27.6 ; 25.274,27.6 U4.26@25.833,27.6 ; U4.26@26.225,27.575 26.704,27.575 26.85,27.429 26.85,26.159 26.85,24.496 26.996,24.35 33.204,24.35 33.35,24.496 33.35,25.746 cw(c33.55,25.746) 33.409,25.887 33.496,25.975 ; C31.2@36.496,28.104 C31.2@36.5,28.1 ; C30.2@36.5,25.7 C30.2@36.516,25.716 ; C30.2@36.5,25.8 36.268,25.568 35.488,25.568 35.056,26 U4.56@34,26 33.975,26.025 33.496,26.025 33.35,26.171 33.35,27.829 33.496,27.975 33.975,27.975 U4.61@34,28 35.213,28 35.412,28.2 C31.2@36.5,28.2
3.3V: C2.2 C4.1 C5.1 C8.2 C17.1 C39.2 C40.2 C41.2 C42.2 C43.2 C44.2 C45.2 C46.2 C47.2 C48.2 C49.2 IC2.1 J4.1 L1.2 L2.1 L3.1 R4.2 R5.2 R21.2 R22.2 R23.2 R24.2 R38.2 U4.13 U4.25 U4.42 U4.43 U4.53 U4.55 U4.59 U4.60 U4.62 U4.64 | length 52.8
  Top Layer w0.152: C43.2@36.5,22.1 36.824,22.424 36.844,22.424 36.996,22.576 37.176,22.576 R21.2@37.5,22.9 v1(38.2,22.9)
  Top Layer w0.2: R5.2@18.1,9 18.15,8.95 18.15,8.35 v1(18.2,8.3) ; C40.2@23.4,28.1 23.425,28.125 24.8,28.125 v1(24.825,28.15) 24.933,28.15 25.083,28 U4.25@26.2,28 ; v1@28.045,33.097 v1(28.08,33.08) cw(c28.277,33.119) 28.096,33.205 28.164,33.349 ccw(c27.983,33.434) 28.125,33.575 C39.2@28.1,33.6 ; v1(28.08,33.08) ccw(c28.277,33.119) 28.096,33.034 28.407,32.376 cw(c28.227,32.29) 28.415,32.357 28.416,32.355 28.456,32.235 cw(c28.267,32.171) 28.467,32.171 28.467,31.985 ccw(c28.667,31.986) 28.47,31.949 cw(c28.225,31.9) 28.475,31.9 28.475,31.8 U4.13@28.5,31.5 ; v1(28.771,20.35) 28.848,20.427 29.077,20.427 C41.2@29.5,20.85 ; C41.2@29.65,20.85 C42.2@30.3,20.85 30.1,21.05 U4.43@30.1,23.7 U4.42@29.7,23.7 ; U4.53@34,24.8 34.025,24.775 34.504,24.775 35.7,23.579 v1(35.7,22.5) 36,22.2 36.4,22.2 C43.2@36.5,22.1 ; U4.55@34,25.6 34.7,25.6 35.292,25.008 36.01,25.008 cw(c36.01,24.808) 36.151,24.949 36.35,24.75 C44.2@36.5,24.6 36.816,24.916 36.816,25.047 v1(36.892,25.123) ; U4.59@34,27.2 U4.60@34,27.6 34.072,27.606 34.183,27.615 cw(c34.2,27.416) 34.239,27.612 34.449,27.57 cw(c34.4,27.325) 34.477,27.563 34.606,27.427 ccw(c34.752,27.564) 34.681,27.377 v1(34.75,27.35) 34.858,27.35 35.138,27.63 36.2,27.63 36.226,27.603 36.297,27.603 C46.2@36.5,27.4 C45.2@36.5,26.6 ; U4.62@34,28.4 35.073,28.4 35.289,28.616 36.062,28.616 36.146,28.7 36.2,28.7 C47.2@36.5,29 36.891,29.391 36.891,29.523 v1(36.967,29.6) ; U4.64@34,29.2 34.74,29.2 35.34,29.8 36.1,29.8 C49.2@36.5,30.2 36.912,30.612 36.912,30.74 v1(36.988,30.816) ; v1(37.5,18.8) R24.2@37.5,19.6 R23.2@37.5,20.4 R22.2@37.5,21.3 ; IC2.1@42.1,25.19 IC2.1@42.25,25.04 42.475,25.04 42.7,25.265 C17.1@42.7,26.4 v1(42.7,27)
  Bottom Layer w0.152: v1(12.3,22) 14.375,24.075 20.625,24.075 20.9,23.8 20.9,20 21.8,19.1 v1(22.4,19.1) ; R38.2@33.3,2.4 33.3,2.926 v1@33.333,2.959
  other v1: 33.3,3 22.4,18.4 23.1,18.4 23.8,18.4 23.1,19.1 23.8,19.1 38.2,23.8 40.9,42.8 40.9,43.4 40.9,44 40.9,44.6
3.3V_1: C7.2 C11.2 C12.1 C18.2 IC2.16 R13.1 R14.1 U1.5 U3.18 U3.19 | length 9.9
  Top Layer w0.152: R13.1@53.4,24.8 R14.1@54.2,24.8 ; U3.18@55.45,27.55 55.5,27.5 v1(55.9,27.5) C12.1@56.5,27.5 56.5,28.276 56.426,28.35 U3.19@56.25,28.35
  Top Layer w0.2: U1.5@49.56,43.8 50.3,43.8 v1(50.7,44.2) ; IC2.16@51.8,25.04 52.075,25.04 52.3,25.265 C18.2@52.3,26.5 51.888,26.912 51.888,27.04 v1(51.812,27.116)
  Top Layer w0.3: R14.1@54.2,24.8 54.3,24.7 54.3,24.45 v1(54.3,23.7)
  Bottom Layer w0.2: C11.2@55.5,25.8 55.5,27.051 55.9,27.451 v1(55.9,27.5)
  other v1: 50.7,43.5 51.4,43.5 52.1,43.5 52.8,43.5 51.4,44.2 52.1,44.2 52.8,44.2
3V3A: C32.2 C33.2 C34.2 C35.2 C36.2 C37.2 C38.2 L3.2 R18.2 R19.2 R20.2 R26.2 R27.2 U4.3 U4.6 U4.8 U4.31 U4.34 U5.5 | length 24.1
  Top Layer w0.2: v1(23.075,25.25) 23.141,25.37 cw(c23.316,25.272) v1@23.158,25.395 ; v1@23.158,25.395 23.174,25.415 ccw(c23.016,25.538) C35.2@23.175,25.417 ; C35.2@23.176,25.418 23.266,25.538 cw(c23.426,25.418) 23.285,25.56 C35.2@23.375,25.65 ; C36.2@23.4,22.9 24.425,22.9 25.925,24.4 U4.34@26.2,24.4 ; C35.2@23.4,25.5 23.84,25.06 25.145,25.06 25.66,25.575 26.175,25.575 U4.31@26.2,25.6 ; U4.8@30.5,31.5 30.525,31.475 30.525,30.996 30.671,30.85 31.129,30.85 31.275,30.996 31.275,31.475 U4.6@31.3,31.5 31.3,33.625 C33.2@31.475,33.8 31.384,33.891 ccw(c31.242,33.75) 31.367,33.906 v1(31.104,34.117) ; U4.3@32.5,31.5 32.5,32.35 33.2,33.05 C32.2@33.2,33.6
  Top Layer w0.3: v1(21,24.9) R19.2@21,25.6 R20.2@21,26.5 ; v1(23.068,23.316) 23.126,23.258 23.126,23.174 C36.2@23.4,22.9 ; R26.2@27.8,37.9 27.85,37.85 28.45,37.85 v1(28.5,37.8) ; R27.2@27.8,40.7 v1(27.8,41.4) ; C32.2@33.2,33.6 33.518,33.918 33.642,33.918 v1(33.7,33.976)
  Bottom Layer w0.3: v1(19.375,36.625) 19.375,36.706 19.6,36.931 R18.2@19.6,37.7 R18.2@19.612,37.688 ; U5.5@22.7,40.55 22.7,41.475 22.994,41.769 v1(25.194,41.769) ; v1@23.068,23.235 v1(23.068,23.316) ; v1@27.719,41.4 v1(27.8,41.4) ; C37.2@33.2,33.6 33.518,33.918 33.642,33.918 v1(33.7,33.976)
  other v1: 27.4,18.3 28.1,18.3 27.4,19 28.1,19
232_CTS: R11.1 U3.2 | length 16
  Top Layer w0.152: U3.2@54.95,31.65 54.95,32.578 56.872,34.5 v1(58,34.5) ; R11.1@58.1,24.481 58.512,24.893 58.512,25.018 v1(58.598,25.104)
  Bottom Layer w0.152: v1(58,34.5) 57.11,33.61 57.11,29.765 57.646,29.229 57.646,28.798 58.626,27.818 58.626,25.132 v1(58.598,25.104)
232_DSR: R7.1 U3.3 | length 23.7
  Top Layer w0.152: U3.3@54.45,31.65 54.45,32.505 56.845,34.9 57.4,34.9 v1(58,35.5) ; v1(57.4,19) R7.1@58.1,19
  Bottom Layer w0.152: v1(57.4,19) 57.4,22.679 57.531,22.81 57.531,26.368 57.344,26.556 57.344,29.104 56.807,29.64 56.807,33.735 57.361,34.289 57.361,34.861 v1(58,35.5)
232_DTR: R12.1 U3.6 | length 15.5
  Top Layer w0.152: U3.6@52.95,31.65 52.95,32.405 55.078,34.534 55.078,34.85 v1(55.164,34.936) ; v1(56.4,25.9) 56.419,25.881 R12.1@58.1,25.881
  Bottom Layer w0.152: v1(55.164,34.936) 55.9,34.2 55.9,29.201 56.426,28.675 56.426,25.926 v1(56.4,25.9)
232_RTS: R9.1 U3.5 | length 21
  Top Layer w0.152: U3.5@53.45,31.65 53.45,32.478 55.944,34.971 55.944,35.444 v1(56,35.5) ; v1(56.4,21.7) 56.419,21.681 R9.1@58.1,21.681
  Bottom Layer w0.152: v1(56,35.5) 56,34.528 56.202,34.325 56.202,29.39 ccw(c56.355,29.39) 56.247,29.282 56.729,28.8 56.729,26.316 56.926,26.118 56.926,25.009 56.4,24.482 v1(56.4,21.7)
232_RX: R8.1 U3.1 | length 18.9
  Top Layer w0.152: U3.1@55.45,31.65 55.45,32.65 56.255,33.455 cw(c56.363,33.348) 56.363,33.5 v1(58.3,33.5) ; R8.1@58.1,20.281 58.514,20.695 58.514,20.825 v1(58.6,20.911)
  Bottom Layer w0.152: v1(58.3,33.5) 57.412,32.612 57.412,29.891 59.1,28.203 59.1,26.131 59.124,26.107 59.124,23.439 58.6,22.915 v1(58.6,20.911)
232_TX: R10.1 U3.4 | length 19.2
  Top Layer w0.152: U3.4@53.95,31.65 53.95,32.55 v1(56.9,35.5) ; v1(56.926,23.1) 58.081,23.1 R10.1@58.1,23.081
  Bottom Layer w0.152: v1(56.9,35.5) 56.9,34.256 56.505,33.86 56.505,29.515 57.041,28.978 57.041,26.431 57.229,26.243 57.229,24.883 56.926,24.581 v1(56.926,23.1)
232CH_GND: C19.1 H2.1 H3.1 J2.10 J2.11 | length 5.9
  Top Layer w1: J2.11@63.299,11.876 J2.11@63.42,11.755
  Top Layer w1.27: C19.1@58.42,11.997 61.109,11.997 62.476,10.63 J2.11@63.42,10.63
  Bottom Layer w1: J2.11@63.299,11.876 J2.11@63.42,11.755
ACT: P2.L2 U4.39 | length 44.7
  Top Layer w0.152: P2.L2@2.1,33.097 3.089,34.086 8.314,34.086 12.802,29.598 16.398,29.598 18.75,31.95 18.75,33.7 18.769,33.719 v1(18.769,33.825) ; v1(28.375,21.25) 28.451,21.326 28.451,23.651 U4.39@28.5,23.7
  Bottom Layer w0.152: v1(18.769,33.825) 19.292,33.302 25.898,33.302 27.455,31.745 cw(c27.348,31.637) 27.5,31.637 27.5,24.735 27.629,24.606 27.629,22.578 28.375,21.832 v1(28.375,21.25)
AT_MODE: SW1.1 U4.20 | length 41.4
  Top Layer w0.152: v1(25.23,30.18) 25.352,30.18 25.532,30 U4.20@26.2,30 ; v1(27.1,14.1) 27.998,13.202 34.37,13.202 34.447,13.125 35.311,12.261 36,11.572 v1(36,9.9)
  Bottom Layer w0.152: v1(25.23,30.18) 26.8,28.611 26.8,17.048 27.1,16.748 v1(27.1,14.1) ; v1(36,9.9) 36,7.042 35.99,7.032 35.99,4.244 36.484,3.75 40.25,3.75 SW1.1@41.5,2.5
BOOT_MODE: SW5.3 U4.21 | length 49.1
  Top Layer w0.152: v1(23.4,33.829) 24.704,32.524 24.704,29.963 25.067,29.6 U4.21@26.2,29.6 ; v1(37.8,33.6) 39.4,32 v1(39.4,30.6) ; v1(44.3,13.2) 44.65,12.85 SW5.3@44.65,12.3
  Bottom Layer w0.152: v1(23.4,33.829) 25.7,33.829 26.384,34.512 26.384,34.828 28.337,36.781 36.519,36.781 37.8,35.5 v1(37.8,33.6) ; v1(39.4,30.6) 40.9,29.1 40.9,15.439 41.839,14.5 43,14.5 v1(44.3,13.2)
CH_GND: C24.2 H1.1 J1.3 P2.R7 P2.S1 P2.S2 | length 85.8
  Top Layer w0.3: P2.S1@10.435,44.272 10.435,36.365 11.823,34.977 P2.R7@15.89,34.977
  Top Layer w1: P2.S2@10.05,29.107 10.1,29.057 10.1,25.8 C24.2@10.125,25.775
  Top Layer w1.27: C24.2@9.52,25.75 H1.1@3.92,25.75 3.945,25.775 C24.2@10.125,25.775
  Bottom Layer w0.5: H1.1@3.92,25.75 3.92,26.69 0.55,30.06 0.55,44.175 1.575,45.2 9.3,45.2 cw(c9.3,44.7) 9.653,45.054 P2.S1@10.05,44.657
  Bottom Layer w1: J1.3@2.984,2.64 J1.3@3.2,2.64 0.8,5.04 0.8,22.63 H1.1@3.92,25.75 ; P2.S2@10.05,29.107 P2.S2@10.275,28.882
  Bottom Layer w2.54: H1.1@3.92,25.75 H1.1@4.721,25.75
CTS: IC2.11 U3.11 | length 13.4
  Top Layer w0.152: IC2.11@51.8,18.69 51.275,18.69 49.39,20.575 49.39,27.418 50.822,28.85 U3.11@52.15,28.85
D_N: R17.2 U4.57 | length 21.6
  Top Layer w0.2: U4.57@34,26.4 35.044,26.4 35.05,26.406 35.319,26.406 35.488,26.237 v1(35.596,26.237) ; 39.724,26.223 39.95,25.997 39.95,15.584 40.9,14.634 40.9,11.2 R17.2@40.7,11
  Bottom Layer w0.2: v1(35.596,26.237) 35.596,26.281 36.216,26.9 39.047,26.9 39.323,26.624
  other v1: 39.4,26.3
D_P: R16.2 U4.58 | length 22.5
  Top Layer w0.2: U4.58@34,26.8 34.879,26.8 34.885,26.806 35.185,26.806 35.354,26.975 v1(35.462,26.975) ; 40.007,26.506 40.35,26.163 40.35,15.75 41.3,14.8 41.3,11.2 R16.2@41.5,11
  Bottom Layer w0.2: v1(35.462,26.975) 35.539,27.052 35.802,27.052 36.05,27.3 39.213,27.3 39.606,26.907 39.854,26.907 v1(39.93,26.83)
DSR: IC2.10 U3.10 | length 15.4
  Top Layer w0.152: IC2.10@51.8,17.42 51.275,17.42 49.088,19.607 49.088,27.543 50.895,29.35 U3.10@52.15,29.35
DTR: IC2.15 U3.7 | length 11.6
  Top Layer w0.152: IC2.15@51.275,23.77 IC2.15@51.8,23.77 51.83,23.8 v1(53.2,23.8) ; v1(51.9,31.8) 51.9,30.924 51.974,30.85 U3.7@52.15,30.85
  Bottom Layer w0.152: v1(51.9,31.8) 52.6,31.1 52.6,28.35 53.2,27.75 v1(53.2,23.8)
FACT_RST: SW4.2 U4.40 | length 21
  Top Layer w0.152: U4.40@28.9,23.7 28.949,23.651 28.949,22.112 v1(29.01,22.05) ; v1(29.1,13.9) 29.705,13.9 30.1,13.505 34.495,13.505 35.7,12.3 SW4.2@39.4,12.3
  Bottom Layer w0.152: v1(29.01,22.05) 29.01,21.964 29.298,21.677 29.298,21.098 29.298,14.4 29.186,14.288 29.186,13.986 v1(29.1,13.9)
GND: C3.1 C4.2 C5.2 C6.1 C8.1 C9.1 C10.2 C17.2 C21.1 C22.1 C24.1 C25.1 C26.1 C27.1 C28.1 C29.1 C30.1 C31.1 C32.1 C33.1 C34.1 C35.1 C36.1 C37.1 C38.1 C39.1 C40.1 C41.1 C42.1 C43.1 C44.1 C45.1 C46.1 C47.1 C48.1 C49.1 C50.1 C51.1 C52.1 C53.1 D3.1 D4.1 D6.1 D7.1 D8.1 IC1.6 IC1.10 IC1.11 IC1.A11 IC1.B11 IC2.8 J1.2 J3.4 J4.5 P1.2 P1.3 R3.1 R6.1 R28.1 R29.1 R30.1 R35.1 SW1.3 SW2.2 SW2.3 SW2.4 SW3.1 SW4.3 SW4.4 SW5.1 U1.1 U2.5 U2.6 U4.22 U4.69 U5.2 Y1.2 Y1.4 Y2.2 Y2.4 | length 21.7
  Top Layer w0.2: U4.22@26.2,29.2 28.5,29.2 v1(30.1,27.6) ; v1(27.2,34.9) 27.308,34.9 27.55,34.658 C39.1@28.042,34.658 ; C39.1@28.032,34.668 C39.1@28.042,34.658 ; C39.1@28.1,34.6 C39.1@28.042,34.658 ; SW3.1@44.6,10.83 44.64,10.79 v1(44.64,9.46)
  Top Layer w0.3: v1@11.756,17.578 11.835,17.5 v1(11.9,17.5) ; C29.1@22.35,27.25 C29.1@22.4,27.3 ; v1(30.2,19) 30.2,19.75 C42.1@30.3,19.85 ; v1(31,19.4) 31,18.876 Y2.2@31.4,18.476 ; C32.1@33.2,34.6 33.493,34.893 33.493,35.218 v1(33.55,35.275) ; v1(33.6,15.9) Y2.4@33.6,16.876 ; v1(34.8,16.5) C52.1@34.8,17.176 ; C44.1@37.5,24.6 v1(38.2,24.6) ; C30.1@37.5,25.9 C30.1@37.5,25.8 37.6,25.7 37.7,25.7 37.743,25.657 38.143,25.657 v1(38.2,25.6) ; C30.1@37.5,26 C45.1@37.5,26.6 ; C31.1@37.5,28.2 37.513,28.213 38.029,28.213 cw(c38.029,27.913) 38.054,28.212 v1(38.2,28.2) ; C47.1@37.5,29 37.505,28.995 38.042,28.995 ccw(c38.042,29.295) 38.052,28.995 v1(38.2,29) ; C49.1@37.5,30.2 v1(38.1,30.2) ; C17.2@41.7,26.4 v1(41.7,27) ; IC2.8@42.25,16.15 IC2.8@42.95,16.2 ; SW4.3@43.175,14.475 43.187,14.463 44.637,14.463 SW5.1@44.65,14.45 ; SW3.1@44.6,10.83 v1(44.6,11.5)
  Bottom Layer w0.3: U5.2@22.7,38.05 22.7,39.119 22.8,39.219 22.8,39.3 ; C37.1@33.2,34.6 33.493,34.893 33.493,35.218 v1(33.55,35.275)
  Bottom Layer w1: J1.2@3.2,6.45 J1.2@3.353,6.603
  other v1: 35.6,1.5 6.54,1.84 9.08,1.84 11.62,1.84 14.16,1.84 16.7,1.84 37.02,1.84 47.18,1.84 52.26,1.84 54.8,1.84 35.6,2.2 35.6,2.9 7,3.075 7.8,3.075 8.6,3.075 14.16,4.38 16.7,4.38 19.24,4.38 26.86,4.38 31.94,4.38 37.02,4.38 39.56,4.38 42.1,4.38 44.64,4.38 49.72,4.38 52.26,4.38 4.9,5.6 4.9,6.4 6.54,6.92 11.62,6.92 47.18,6.92 49.72,6.92 52.26,6.92 54.8,6.92 4.9,7.2 33.3,8.6 34,8.6 34.7,8.6 42.4,9.3 14.16,9.46 39.56,9.46 42.4,10 39.6,10.2 42.4,10.7 39.6,10.9 33.2,11.8 34.4,11.8 4,12 6.54,12 9.08,12 20.6,12.4 21.3,12.4 20.6,13.1 21.3,13.1 39,13.4 42.1,13.4 42.8,13.4 20.6,13.8 21.3,13.8 20.6,14.5 21.3,14.5 4,14.54 11.62,14.54 31.94,14.54 37.02,14.54 28.2,15 5.6,15.2 6.3,15.2 7.1,15.2 7.9,15.2 42,15.3 42.7,15.3 22.552,15.365 22.552,16.065 17,16.2 22.552,16.765 17,16.9 6.54,17.08 5.4,17.4 12.6,17.5 13.3,17.5 14,17.5 14.7,17.5 15.4,17.5 16.1,17.5 5.4,18.2 5.4,19 6.54,19.62 5.4,19.8 27.8,20.3 21.6,20.5 22.3,20.5 33.2,21.1 21.6,21.3 21.6,22.1 32,22.5 12.7,24.1 12.7,24.8 12.7,25.5 28.054,25.546 29.054,25.546 30.054,25.546 31.054,25.546 32.054,25.546 12.7,26.2 28.077,26.573 29.077,26.573 30.077,26.573 31.077,26.573 32.077,26.573 12.7,26.9 28.1,27.6 29.1,27.6 31.1,27.6 32.1,27.6 22,27.7 28.123,28.627 29.123,28.627 30.123,28.627 31.123,28.627 32.123,28.627 18.725,28.725 18.725,29.425 28.146,29.654 29.146,29.654 30.146,29.654 31.146,29.654 32.146,29.654 22.3,30.6 22.3,31.5 21.65,32.4 29.125,34.625 37.02,34.86 39.56,34.86 20.6,35.8 20.6,36.5 20.6,37.2 26.86,37.4 37.02,37.4 39.56,37.4 29.8,37.6 31.8,37.6 43,37.9 43,38.7 43.8,39.3 44.6,39.3 34.48,39.94 37.02,39.94 39.56,39.94 43.4,40.1 18.8,40.7 20.3,40.7 43.4,40.9 26.4,41 30,41 32,41 43.4,41.7 24.32,42.48 37.02,42.48 39.56,42.48 43.4,42.5 43.8,45 44.6,45
GND_1: C7.1 C10.1 C11.1 C12.2 C14.1 C16.1 C18.1 C19.2 IC2.9 J2.5 R15.1 U1.4 U3.17 U3.25 | length 3.1
  Top Layer w0.2: v1(50.5,26.5) C18.1@51.3,26.5 ; C12.2@57.5,27.5 57.55,27.55 58.05,27.55 v1(58.1,27.6) ; C16.1@57.5,32.9 57.912,32.488 58.04,32.488 v1(58.116,32.412) ; v1(58.2,30) 58.2,29.892 58.35,29.742 58.35,29.45 C14.1@58.5,29.3
  other v1: 53.2,11.3 53.2,12 52.14,12.087 53.2,12.7 52.14,14.627 54.68,14.627 57.22,14.627 49.6,17.167 54.68,17.167 57.22,17.167 54.68,19.707 54.68,22.247 53.5,28.9 54.2,28.9 54.9,28.9 53.5,29.6 54.2,29.6 54.9,29.6 53.5,30.3 54.2,30.3 54.9,30.3 52.14,34.947 49.6,37.487 52.14,37.487 54.68,37.487 57.22,37.487 52.14,40.027 54.68,40.027 57.22,40.027 50.2,40.3 50.2,41 50.2,41.7 54.68,42.567 57.22,42.567
LINK: P2.L4 U4.37 | length 44.3
  Top Layer w0.152: P2.L4@2.1,43.207 2.141,43.207 2.848,42.5 4.1,42.5 5.1,41.5 5.1,39.834 12.497,32.437 13.963,32.437 15.15,31.25 16.75,31.25 v1(17.6,32.1) ; v1(27.326,21.726) 27.326,22.854 27.651,23.179 27.651,23.651 U4.37@27.7,23.7
  Bottom Layer w0.152: v1(17.6,32.1) 18.425,32.925 cw(c18.533,32.817) 18.533,32.97 25.803,32.97 27.153,31.619 cw(c27.045,31.512) 27.198,31.512 27.198,24.546 27.326,24.418 v1(27.326,21.726)
MDI_R1_N: C23.1 R33.2 R36.2 | length 4
  Top Layer w0.2: C23.1@24.9,36.4 25.1,36.2 25.5,36.2 R36.2@25.7,36.4 25.9,36.2 28.4,36.2 R33.2@28.6,36.4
